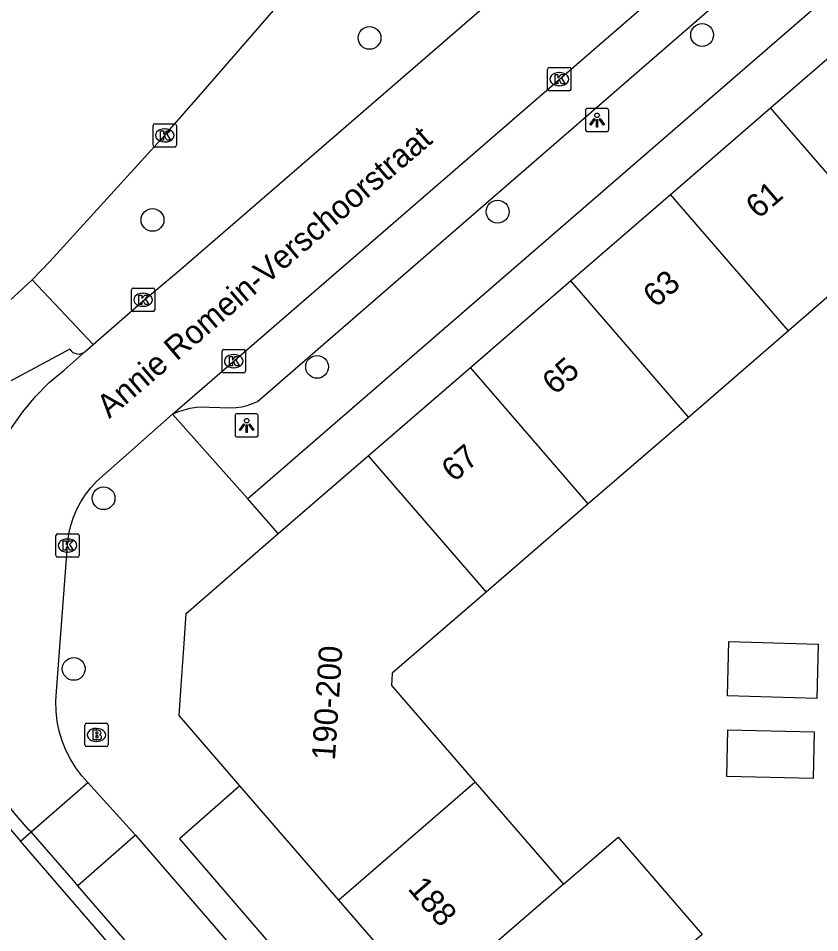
# Model space of a CAD drawing. Extents: x 160304 to 160954, y 383686 to 384161.
# Drawn here: x 160359.73 to 160394.06, y 384042.77 to 384081.93 of the extents above; entities that cross this region are included whole.
import ezdxf

# ---------------------------------------------------------------- set-up
doc = ezdxf.new("R2010")
doc.units = 0
for name, color, linetype in [('IMGEO_Berm_groen', 7, 'Continuous'), ('IMGEO_Boom', 7, 'Continuous'), ('IMGEO_Brandkraan', 7, 'Continuous'), ('IMGEO_Fietspad_gesloten', 7, 'Continuous'), ('IMGEO_Kolk', 7, 'Continuous'), ('IMGEO_Lichtpunt', 7, 'Continuous'), ('IMGEO_Openbare_ruimte_label', 7, 'Continuous'), ('IMGEO_Pand', 7, 'Continuous'), ('IMGEO_Pand_nummerreeks', 7, 'Continuous'), ('IMGEO_Rijbaan_lokaal_gesloten', 7, 'Continuous'), ('IMGEO_Rijbaan_lokaal_open', 7, 'Continuous'), ('IMGEO_Voetpad_open', 7, 'Continuous')]:
    doc.layers.add(name, color=color, linetype=linetype)

msp = doc.modelspace()

# ---------------------------------------------------------------- linework, layer by layer
at = {"layer": 'IMGEO_Berm_groen'}
msp.add_lwpolyline([(160362.943, 384067.958), (160360.319, 384070.736)], dxfattribs=at)
at = {"layer": 'IMGEO_Boom'}
for centre in [(160389.026, 384081.218), (160374.777, 384081.092), (160380.264, 384073.648), (160365.479, 384073.297), (160372.531, 384067.002), (160363.383, 384061.375), (160362.105, 384054.066)]:
    msp.add_circle(centre, 0.489, dxfattribs=at)
at = {"layer": 'IMGEO_Brandkraan'}
for p, q in [((160362.579, 384050.809), (160362.579, 384051.661)), ((160362.654, 384051.735), (160363.506, 384051.735)), ((160363.58, 384051.661), (160363.58, 384050.809)), ((160363.067, 384051.515), (160363.092, 384051.515)), ((160363.09, 384050.955), (160363.065, 384050.955)), ((160363.506, 384050.735), (160362.654, 384050.735))]:
    msp.add_line(p, q, dxfattribs=at)
for points in [[(160362.579, 384050.809), (160362.579, 384051.661)], [(160362.654, 384051.735), (160363.506, 384051.735)], [(160363.58, 384051.661), (160363.58, 384050.809)], [(160362.927, 384051.435), (160362.927, 384051.035), (160363.14, 384051.035)], [(160363.158, 384051.435), (160362.927, 384051.435)], [(160363.106, 384051.354), (160363.052, 384051.354), (160363.052, 384051.278)], [(160363.052, 384051.278), (160363.105, 384051.278)], [(160363.114, 384051.202), (160363.052, 384051.202), (160363.052, 384051.121)], [(160363.052, 384051.121), (160363.114, 384051.121)], [(160363.506, 384050.735), (160362.654, 384050.735)]]:
    msp.add_lwpolyline(points, dxfattribs=at)
for centre, radius, start, end in [((160362.656, 384051.659), 0.0765, 91.552, 178.448), ((160362.656, 384051.659), 0.0765, 91.552, 178.448), ((160363.504, 384051.659), 0.0765, 1.552, 88.448), ((160363.504, 384051.659), 0.0765, 1.552, 88.448), ((160363.107, 384051.316), 0.0379, 267.8285, 90.9355), ((160363.115, 384051.161), 0.0404, 269.8759, 90.5077), ((160363.162, 384051.29), 0.145, 59.4692, 91.5367), ((160363.187, 384051.337), 0.0922, 285.5137, 58.1501), ((160363.192, 384051.145), 0.105, 301.3115, 78.989), ((160362.656, 384050.811), 0.0765, 181.552, 268.448), ((160362.656, 384050.811), 0.0765, 181.552, 268.448), ((160363.146, 384051.286), 0.251, 268.6676, 293.5347), ((160363.504, 384050.811), 0.0765, 271.552, 358.448), ((160363.504, 384050.811), 0.0765, 271.552, 358.448)]:
    msp.add_arc(centre, radius, start, end, dxfattribs=at)
for centre, major_axis, ratio, start_param, end_param in [((160363.066, 384051.235), (-0.387, 0.002), 0.722429, 4.712389, 7.853982), ((160363.091, 384051.235), (-0.39, 0.002), 0.717154, 1.570796, 4.712389)]:
    msp.add_ellipse(centre, major_axis=major_axis, ratio=ratio, start_param=start_param, end_param=end_param, dxfattribs=at)
at = {"layer": 'IMGEO_Fietspad_gesloten'}
msp.add_lwpolyline([(160361.931, 384067.756), (160358.547, 384065.941), (160355.612, 384064.617)], dxfattribs=at)
msp.add_arc((160362.31, 384068.007), 0.455, 213.5501, 308.815, dxfattribs=at)
at = {"layer": 'IMGEO_Kolk'}
for p, q in [((160382.407, 384078.899), (160382.407, 384079.751)), ((160382.482, 384079.825), (160383.334, 384079.825)), ((160383.408, 384079.751), (160383.408, 384078.899)), ((160382.895, 384079.605), (160382.92, 384079.605)), ((160382.918, 384079.045), (160382.893, 384079.045)), ((160383.334, 384078.825), (160382.482, 384078.825)), ((160365.579, 384077.418), (160366.431, 384077.418)), ((160365.504, 384076.492), (160365.504, 384077.344)), ((160365.992, 384077.198), (160366.017, 384077.198)), ((160366.505, 384077.344), (160366.505, 384076.492)), ((160366.015, 384076.638), (160365.99, 384076.638)), ((160366.431, 384076.418), (160365.579, 384076.418)), ((160364.649, 384070.376), (160365.501, 384070.376)), ((160364.574, 384069.45), (160364.574, 384070.302)), ((160365.062, 384070.156), (160365.087, 384070.156)), ((160365.575, 384070.302), (160365.575, 384069.45)), ((160365.085, 384069.596), (160365.06, 384069.596)), ((160365.501, 384069.376), (160364.649, 384069.376)), ((160368.458, 384066.819), (160368.458, 384067.671)), ((160368.533, 384067.745), (160369.385, 384067.745)), ((160369.459, 384067.671), (160369.459, 384066.819)), ((160368.946, 384067.525), (160368.971, 384067.525)), ((160368.969, 384066.965), (160368.944, 384066.965)), ((160369.385, 384066.745), (160368.533, 384066.745)), ((160361.338, 384058.923), (160361.338, 384059.775)), ((160361.413, 384059.849), (160362.265, 384059.849)), ((160362.339, 384059.775), (160362.339, 384058.923)), ((160361.826, 384059.629), (160361.851, 384059.629)), ((160361.849, 384059.069), (160361.824, 384059.069)), ((160362.265, 384058.849), (160361.413, 384058.849))]:
    msp.add_line(p, q, dxfattribs=at)
for points in [[(160382.407, 384078.899), (160382.407, 384079.751)], [(160382.482, 384079.825), (160383.334, 384079.825)], [(160383.408, 384079.751), (160383.408, 384078.899)], [(160382.728, 384079.525), (160382.851, 384079.525), (160382.851, 384079.374), (160382.981, 384079.525), (160383.145, 384079.525), (160382.999, 384079.374), (160383.152, 384079.125), (160383, 384079.125), (160382.915, 384079.289), (160382.851, 384079.222), (160382.851, 384079.125), (160382.728, 384079.125), (160382.728, 384079.525)], [(160383.334, 384078.825), (160382.482, 384078.825)], [(160365.579, 384077.418), (160366.431, 384077.418)], [(160365.504, 384076.492), (160365.504, 384077.344)], [(160365.825, 384077.118), (160365.948, 384077.118), (160365.948, 384076.967), (160366.078, 384077.118), (160366.242, 384077.118), (160366.096, 384076.967), (160366.249, 384076.718), (160366.097, 384076.718), (160366.012, 384076.882), (160365.948, 384076.815), (160365.948, 384076.718), (160365.825, 384076.718), (160365.825, 384077.118)], [(160366.505, 384077.344), (160366.505, 384076.492)], [(160366.431, 384076.418), (160365.579, 384076.418)], [(160364.649, 384070.376), (160365.501, 384070.376)], [(160364.574, 384069.45), (160364.574, 384070.302)], [(160364.895, 384070.076), (160365.018, 384070.076), (160365.018, 384069.925), (160365.148, 384070.076), (160365.312, 384070.076), (160365.166, 384069.925), (160365.319, 384069.676), (160365.167, 384069.676), (160365.082, 384069.84), (160365.018, 384069.773), (160365.018, 384069.676), (160364.895, 384069.676), (160364.895, 384070.076)], [(160365.575, 384070.302), (160365.575, 384069.45)], [(160365.501, 384069.376), (160364.649, 384069.376)], [(160368.458, 384066.819), (160368.458, 384067.671)], [(160368.533, 384067.745), (160369.385, 384067.745)], [(160369.459, 384067.671), (160369.459, 384066.819)], [(160368.779, 384067.445), (160368.902, 384067.445), (160368.902, 384067.294), (160369.032, 384067.445), (160369.196, 384067.445), (160369.05, 384067.294), (160369.203, 384067.045), (160369.051, 384067.045), (160368.966, 384067.209), (160368.902, 384067.142), (160368.902, 384067.045), (160368.779, 384067.045), (160368.779, 384067.445)], [(160369.385, 384066.745), (160368.533, 384066.745)], [(160361.338, 384058.923), (160361.338, 384059.775)], [(160361.413, 384059.849), (160362.265, 384059.849)], [(160362.339, 384059.775), (160362.339, 384058.923)], [(160361.659, 384059.549), (160361.782, 384059.549), (160361.782, 384059.398), (160361.912, 384059.549), (160362.076, 384059.549), (160361.93, 384059.398), (160362.083, 384059.149), (160361.931, 384059.149), (160361.846, 384059.313), (160361.782, 384059.246), (160361.782, 384059.149), (160361.659, 384059.149), (160361.659, 384059.549)], [(160362.265, 384058.849), (160361.413, 384058.849)]]:
    msp.add_lwpolyline(points, dxfattribs=at)
for centre, start, end in [((160382.484, 384079.749), 91.552, 178.448), ((160382.484, 384079.749), 91.552, 178.448), ((160383.332, 384079.749), 1.552, 88.448), ((160383.332, 384079.749), 1.552, 88.448), ((160382.484, 384078.901), 181.552, 268.448), ((160382.484, 384078.901), 181.552, 268.448), ((160383.332, 384078.901), 271.552, 358.448), ((160383.332, 384078.901), 271.552, 358.448), ((160365.581, 384077.342), 91.552, 178.448), ((160365.581, 384077.342), 91.552, 178.448), ((160366.429, 384077.342), 1.552, 88.448), ((160366.429, 384077.342), 1.552, 88.448), ((160365.581, 384076.494), 181.552, 268.448), ((160365.581, 384076.494), 181.552, 268.448), ((160366.429, 384076.494), 271.552, 358.448), ((160366.429, 384076.494), 271.552, 358.448), ((160364.651, 384070.3), 91.552, 178.448), ((160364.651, 384070.3), 91.552, 178.448), ((160365.499, 384070.3), 1.552, 88.448), ((160365.499, 384070.3), 1.552, 88.448), ((160364.651, 384069.452), 181.552, 268.448), ((160364.651, 384069.452), 181.552, 268.448), ((160365.499, 384069.452), 271.552, 358.448), ((160365.499, 384069.452), 271.552, 358.448), ((160368.535, 384067.669), 91.552, 178.448), ((160368.535, 384067.669), 91.552, 178.448), ((160369.383, 384067.669), 1.552, 88.448), ((160369.383, 384067.669), 1.552, 88.448), ((160368.535, 384066.821), 181.552, 268.448), ((160368.535, 384066.821), 181.552, 268.448), ((160369.383, 384066.821), 271.552, 358.448), ((160369.383, 384066.821), 271.552, 358.448), ((160361.415, 384059.773), 91.552, 178.448), ((160361.415, 384059.773), 91.552, 178.448), ((160362.263, 384059.773), 1.552, 88.448), ((160362.263, 384059.773), 1.552, 88.448), ((160361.415, 384058.925), 181.552, 268.448), ((160361.415, 384058.925), 181.552, 268.448), ((160362.263, 384058.925), 271.552, 358.448), ((160362.263, 384058.925), 271.552, 358.448)]:
    msp.add_arc(centre, 0.0765, start, end, dxfattribs=at)
for centre, major_axis, ratio, start_param, end_param in [((160382.894, 384079.325), (-0.387, 0.002), 0.722429, 4.712389, 7.853982), ((160382.919, 384079.325), (-0.39, 0.002), 0.717154, 1.570796, 4.712389), ((160365.991, 384076.918), (-0.387, 0.002), 0.722429, 4.712389, 7.853982), ((160366.016, 384076.918), (-0.39, 0.002), 0.717154, 1.570796, 4.712389), ((160365.061, 384069.876), (-0.387, 0.002), 0.722429, 4.712389, 7.853982), ((160365.086, 384069.876), (-0.39, 0.002), 0.717154, 1.570796, 4.712389), ((160368.945, 384067.245), (-0.387, 0.002), 0.722429, 4.712389, 7.853982), ((160368.97, 384067.245), (-0.39, 0.002), 0.717154, 1.570796, 4.712389), ((160361.825, 384059.349), (-0.387, 0.002), 0.722429, 4.712389, 7.853982), ((160361.85, 384059.349), (-0.39, 0.002), 0.717154, 1.570796, 4.712389)]:
    msp.add_ellipse(centre, major_axis=major_axis, ratio=ratio, start_param=start_param, end_param=end_param, dxfattribs=at)
at = {"layer": 'IMGEO_Lichtpunt'}
for p, q in [((160384.027, 384077.978), (160384.027, 384077.171)), ((160384.027, 384077.978), (160384.027, 384077.171)), ((160384.929, 384078.073), (160384.121, 384078.073)), ((160384.929, 384078.073), (160384.121, 384078.073)), ((160385.023, 384077.171), (160385.023, 384077.978)), ((160385.023, 384077.171), (160385.023, 384077.978)), ((160384.121, 384077.077), (160384.929, 384077.077)), ((160384.121, 384077.077), (160384.929, 384077.077)), ((160369.014, 384064.9), (160369.014, 384064.093)), ((160369.014, 384064.9), (160369.014, 384064.093)), ((160369.916, 384064.995), (160369.108, 384064.995)), ((160369.916, 384064.995), (160369.108, 384064.995)), ((160370.01, 384064.093), (160370.01, 384064.9)), ((160370.01, 384064.093), (160370.01, 384064.9)), ((160369.108, 384063.999), (160369.916, 384063.999)), ((160369.108, 384063.999), (160369.916, 384063.999))]:
    msp.add_line(p, q, dxfattribs=at)
for points in [[(160384.401, 384077.642), (160384.44, 384077.614), (160384.252, 384077.352), (160384.214, 384077.379), (160384.401, 384077.642)], [(160384.503, 384077.594), (160384.55, 384077.594), (160384.55, 384077.272), (160384.503, 384077.272), (160384.503, 384077.594)], [(160384.613, 384077.614), (160384.651, 384077.641), (160384.838, 384077.379), (160384.799, 384077.351), (160384.613, 384077.614)], [(160369.388, 384064.564), (160369.427, 384064.536), (160369.239, 384064.274), (160369.201, 384064.301), (160369.388, 384064.564)], [(160369.49, 384064.516), (160369.537, 384064.516), (160369.537, 384064.194), (160369.49, 384064.194), (160369.49, 384064.516)], [(160369.6, 384064.536), (160369.638, 384064.563), (160369.825, 384064.301), (160369.786, 384064.273), (160369.6, 384064.536)]]:
    msp.add_lwpolyline(points, dxfattribs=at)
for centre in [(160384.526, 384077.776), (160369.513, 384064.698)]:
    msp.add_circle(centre, 0.0994, dxfattribs=at)
for centre, start, end in [((160384.121, 384077.978), 90, 180), ((160384.121, 384077.978), 90, 180), ((160384.929, 384077.978), 0, 90), ((160384.929, 384077.978), 0, 90), ((160384.121, 384077.171), 180, 270), ((160384.121, 384077.171), 180, 270), ((160384.929, 384077.171), 270, 0), ((160384.929, 384077.171), 270, 360), ((160369.108, 384064.9), 90, 180), ((160369.108, 384064.9), 90, 180), ((160369.916, 384064.9), 0, 90), ((160369.916, 384064.9), 0, 90), ((160369.108, 384064.093), 180, 270), ((160369.108, 384064.093), 180, 270), ((160369.916, 384064.093), 270, 0), ((160369.916, 384064.093), 270, 360)]:
    msp.add_arc(centre, 0.0946, start, end, dxfattribs=at)
at = {"layer": 'IMGEO_Pand'}
for points in [[(160391.96, 384078.097), (160396.247, 384081.804)], [(160387.672, 384074.39), (160391.96, 384078.097)], [(160397.013, 384072.253), (160391.96, 384078.097)], [(160383.385, 384070.682), (160387.672, 384074.39)], [(160392.724, 384068.546), (160387.672, 384074.39)], [(160397.013, 384072.253), (160392.724, 384068.546)], [(160379.098, 384066.975), (160383.385, 384070.682)], [(160383.385, 384070.682), (160388.436, 384064.84)], [(160392.724, 384068.546), (160388.436, 384064.84)], [(160374.719, 384063.189), (160379.098, 384066.975)], [(160384.148, 384061.134), (160379.098, 384066.975)], [(160388.436, 384064.84), (160384.148, 384061.134)], [(160370.867, 384059.859), (160374.719, 384063.189)], [(160374.719, 384063.189), (160379.769, 384057.349)], [(160384.148, 384061.134), (160379.769, 384057.349)], [(160369.22, 384049.062), (160366.625, 384052.063), (160366.712, 384053.361), (160366.832, 384055.157), (160366.918, 384056.444), (160370.867, 384059.859)], [(160379.769, 384057.349), (160375.75, 384053.876), (160375.721, 384053.359), (160379.304, 384049.215)], [(160390.108, 384052.908), (160390.173, 384055.233), (160394, 384055.125), (160393.935, 384052.8), (160390.108, 384052.908)], [(160390.083, 384049.455), (160390.13, 384051.449), (160393.827, 384051.363), (160393.781, 384049.369), (160390.083, 384049.455)], [(160379.304, 384049.215), (160373.455, 384044.164)], [(160379.304, 384049.215), (160383.087, 384044.841)], [(160373.455, 384044.164), (160369.22, 384049.062)], [(160383.087, 384044.841), (160385.422, 384046.86), (160389.03, 384042.688), (160386.695, 384040.669), (160386.794, 384040.554)], [(160383.087, 384044.841), (160377.241, 384039.785)], [(160377.241, 384039.785), (160373.455, 384044.164)]]:
    msp.add_lwpolyline(points, dxfattribs=at)
at = {"layer": 'IMGEO_Rijbaan_lokaal_gesloten'}
for points in [[(160360.319, 384070.736), (160361.087, 384071.52), (160366.004, 384076.919), (160367.654, 384078.8), (160378.757, 384091.601), (160391.585, 384107.888)], [(160351.994, 384063.019), (160352.168, 384063.187), (160360.319, 384070.736)]]:
    msp.add_lwpolyline(points, dxfattribs=at)
at = {"layer": 'IMGEO_Rijbaan_lokaal_open'}
for points in [[(160362.943, 384067.958), (160365.075, 384069.831), (160366.686, 384071.182), (160385.508, 384087.482)], [(160366.337, 384064.976), (160388.431, 384084.109)], [(160358.712, 384062.966), (160359.024, 384063.647), (160359.44, 384064.385), (160359.921, 384065.083), (160360.462, 384065.735), (160361.059, 384066.336), (160361.698, 384066.865), (160362.595, 384067.653)], [(160362.595, 384067.653), (160362.943, 384067.958)], [(160362.707, 384049.198), (160362.453, 384049.48), (160362.192, 384049.825), (160361.962, 384050.192), (160361.766, 384050.578), (160361.606, 384050.98), (160361.482, 384051.394), (160361.395, 384051.818), (160361.347, 384052.248), (160361.337, 384052.681), (160361.366, 384053.113), (160361.837, 384059.349), (160361.866, 384059.607), (160361.901, 384059.855), (160361.981, 384060.214), (160362.091, 384060.564), (160362.233, 384060.903), (160362.405, 384061.228), (160362.604, 384061.536), (160362.831, 384061.826), (160363.083, 384062.094), (160363.357, 384062.338), (160366.337, 384064.976)], [(160360.274, 384047.085), (160360.185, 384047.175), (160359.532, 384047.909), (160358.947, 384048.697), (160358.434, 384049.535), (160357.999, 384050.416), (160357.644, 384051.331), (160357.372, 384052.275), (160357.237, 384053.449), (160357.176, 384055.08), (160357.261, 384056.709), (160357.491, 384058.325)], [(160360.274, 384047.085), (160362.707, 384049.198)], [(160362.707, 384049.198), (160364.754, 384046.943)], [(160362.283, 384044.777), (160362.095, 384044.995), (160360.274, 384047.085)], [(160364.754, 384046.943), (160362.283, 384044.777)], [(160364.754, 384046.943), (160397.588, 384008.955)], [(160370.313, 384035.491), (160362.283, 384044.777)]]:
    msp.add_lwpolyline(points, dxfattribs=at)
at = {"layer": 'IMGEO_Voetpad_open'}
for points in [[(160420.868, 384105.779), (160369.56, 384061.353)], [(160366.337, 384064.976), (160366.57, 384065.079), (160366.829, 384065.167), (160367.094, 384065.232), (160367.365, 384065.273), (160367.638, 384065.29), (160367.912, 384065.282), (160368.819, 384065.249), (160369.062, 384065.261), (160369.302, 384065.296), (160369.539, 384065.351), (160369.77, 384065.428), (160369.98, 384065.518), (160413.547, 384103.317)], [(160369.56, 384061.353), (160366.337, 384064.976)], [(160370.867, 384059.859), (160369.56, 384061.353)], [(160336.228, 384040.312), (160342.207, 384044.937), (160344.09, 384046.619), (160346.951, 384049.435), (160352.956, 384054.651), (160358.706, 384047.974), (160359.817, 384046.689)], [(160369.22, 384049.062), (160366.633, 384046.782), (160406.925, 384000), (160415.887, 383989.594), (160418.503, 383989.954)], [(160359.817, 384046.689), (160360.274, 384047.085)], [(160372.913, 384022.406), (160365.964, 384030.447), (160369.372, 384033.427), (160369.466, 384033.534), (160369.55, 384033.649), (160369.624, 384033.771), (160369.686, 384033.899), (160369.736, 384034.033), (160369.775, 384034.17), (160369.801, 384034.31), (160369.814, 384034.452), (160369.815, 384034.594), (160369.803, 384034.736), (160369.778, 384034.876), (160369.741, 384035.014), (160369.692, 384035.148), (160369.631, 384035.276), (160369.559, 384035.399), (160369.476, 384035.515), (160369.405, 384035.599), (160363.882, 384041.987), (160359.817, 384046.689)]]:
    msp.add_lwpolyline(points, dxfattribs=at)

# ---------------------------------------------------------------- texts
at = {"layer": 'IMGEO_Openbare_ruimte_label'}
msp.add_text('Annie Romein-Verschoorstraat', height=1, rotation=40.4956, dxfattribs=at).set_placement((160363.627, 384064.764))
at = {"layer": 'IMGEO_Pand_nummerreeks'}
for s, rotation, p in [('61', 40.8519, (160391.439, 384073.309)), ('63', 40.8519, (160387.036, 384069.501)), ('65', 40.8519, (160382.718, 384065.767)), ('67', 40.8519, (160378.4, 384062.033)), ('190-200', 86.1786, (160373.293, 384050.13)), ('188', 310.8517, (160376.381, 384044.636))]:
    msp.add_text(s, height=1, rotation=rotation, dxfattribs=at).set_placement(p)

doc.saveas('drawing.dxf')
